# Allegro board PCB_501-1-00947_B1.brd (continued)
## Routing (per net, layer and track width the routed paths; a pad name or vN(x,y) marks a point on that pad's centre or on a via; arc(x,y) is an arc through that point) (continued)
GND_USB_A: length 27.7
  BOTTOM w0.508: J26.S4 45.09,24.7 C301.1 R250.1
  BOTTOM w1.524: J26.S1 J26.S3 41.44,21.14 43.31,21.14 J26.S4 J26.S2
GND_USB_CONN: length 14.5
  TOP w0.381: J11.S1 126.18,104.97 J11.S4 J11.S5 J11.S6 128.53,111.47 ; C242.1 R163.1 125.73,111.81 J11.S2 128.53,111.47 ; 128.53,111.47 J11.S3
PVCC_ENET_CAP: length 1.5
  TOP w0.254: U7.H14 57.46,84.18 v2(57.28,84.36)
  BOTTOM w0.254: C115.1 57.73,83.91 v2(57.28,84.36)
PVCC_EPDC_LCD_CAP: length 1.4
  TOP w0.254: v2(59.36,88.42) U7.N17
  BOTTOM w0.305: v2(59.36,88.42) 59.36,87.77 C116.1
PVCC_GPIO_CAP: length 1.6
  TOP w0.305: U7.V10 64.84,87.36 v2(64.71,87.48)
  BOTTOM w0.305: v2(64.71,87.48) 63.99,88.2 C100.1
PVCC_I2C_SPI_UART_CAP: length 2.1
  TOP w0.102: 63.68,85.24 U7.R9
  TOP w0.254: v2(63.68,85.24) 63.68,85.24 U7.R9
  BOTTOM w0.254: v2(63.68,85.24) 63.26,85.66 C128.1
PVCC_SAI_SD_CAP: length 1.4
  TOP w0.254: U7.J9 61.16,81.89 61.16,81.58 v2(61.13,81.56)
  BOTTOM w0.254: v2(61.13,81.56) 61.47,81.9 61.84,81.9
VCCI_EMMC: length 1.2
  TOP w0.081: U10.C2 70.9,63.44 70.37,63.97 70.37,64.02 v1(70.32,64.06)
VDD_1P2_CAP: length 2.3
  TOP w0.254: U7.H12 58.87,83.62 v2(58.86,83.63) ; v2(64.76,86.3) U7.U9
  BOTTOM w0.254: v2(58.86,83.63) 58.88,83.65 58.98,83.65 C88.1 ; C89.1 64.76,86.54 v2(64.76,86.3)
VDD_1V8: length 212.5
  TOP w0.152: U5.39 15.08,82.42 v1(14.93,82.27)
  TOP w0.254: U50.1 10.8,67.52 8.72,69.61 8.72,75.1 8.94,75.32 9.58,75.32 10.18,74.72 ; R682.2 v1(102.84,12.32)
  TOP w0.305: v2(61.54,82.92) 61.74,83.11 U7.L9 v2(62.54,83.11) ; U45.3 26.44,56.58 26.33,56.7 C461.1 25.68,56.51 v1(25.27,56.1) 24.71,55.54 R639.1 ; v1(75.66,92.15) 75.66,92.15 75.66,92.08 75.61,92.02 74.53,92.02 R607.1 ; v1(72.84,94.76) 72.81,94.74 72.49,94.74 R605.1 ; 81.46,99.15 U42.3 ; v1(77.38,99.36) 76.87,99.86 C407.1 76.49,99.84 76.49,99.41 77.58,98.31 ; 78.55,100.17 79,99.73 ; 80.74,95.12 80.27,95.59 U42.20 ; R638.1 R640.2
  TOP w0.381: R638.1 33.77,55.01 v1(33.88,55.12)
  TOP w0.457: M1.38 121.07,15.17 121.07,15.16
  TOP w0.508: 78.55,100.17 77.91,100.82 C509.1 77.97,101.13 C406.1 78.97,102.11 v1(79.6,102.74) ; v1(122.27,9.02) 122.14,9.02 121.75,8.63 121.75,8.5 121.74,8.49 FB39.2 ; 121.07,15.16 C216.1 v1(123.23,15.16) ; v1(82.01,93.55) C409.1 80.74,94.82 80.74,95.12 ; FB36.2 v1(5.83,38.33) ; 81.46,99.15 81.46,99.48 C410.1 81.72,99.78 v1(82.2,100.27) ; v3(77.83,73.28) 77.8,73.28 R45.1 78.66,72.42 79.46,73.22 R325.1 78.86,73.85 v3(78.37,73.85) ; C574.1 v1(89.45,51.82)
  L3_INT_1 w0.254: v1(20.99,75.89) 19.87,75.89 15.63,80.13 15.63,81.58 v1(14.93,82.27)
  L4_PWR_1 w0.254: v1(20.99,75.89) 20.99,75.87 19.59,74.46 19.59,70.58 20.51,69.66 25.4,69.66 35.02,79.28 35.02,85.41 38.58,88.97 52.8,88.97 53.81,89.98 54.23,89.98 54.69,90.44 56.09,90.44 56.98,89.55 59.57,89.55 59.71,89.42 61.37,89.42 61.66,89.71 62.97,89.71 63.3,90.04 64.29,90.04 66.79,87.53 66.79,86.62 65.27,85.09 65.27,83.45 64.49,82.67
  BOTTOM w0.178: 102.55,63.5 U55.A2
  BOTTOM w0.254: v3(80.54,81.18) 79.75,80.39 77.44,80.39 76.28,81.55 R32.1 ; 126.08,30.35 99.41,30.35 96.89,27.84 96.89,12.81 97.65,12.05 102.57,12.05 v1(102.84,12.32) 102.84,12.45 102.81,12.47 R710.2 R709.2 R708.2 R707.2 R711.2
  BOTTOM w0.305: v2(62.54,83.11) 63.08,83.65 63.08,83.83
  BOTTOM w0.381: Q39.1 12.72,50.37 R636.2 v1(12.67,49.66)
  BOTTOM w0.406: FB35.1 5.66,51.65 6.53,50.77 7.93,50.77 9.52,52.36 12.13,52.36 12.72,51.78 Q39.1
  BOTTOM w0.508: C575.1 88.9,48.39 v1(89.45,48.93)
  BOTTOM w0.635: v1(101.39,62.68) C561.1 102.55,63.5
  vias: v1(25.28,53.51) v1(25.3,52.13) v1(29.28,56.33) v1(114.65,48.77) v1(114.65,47.12) v1(114.65,45.47) v1(115.41,49.28) v1(115.41,47.62) v1(115.41,45.97) v3(11.41,73.8) v3(11.44,71.16) v3(11.49,69.75) v3(11.46,68.46) v3(12.54,72.52) v3(12.59,69.77) v3(12.54,68.45) v3(14.83,72.52) v3(14.83,71.12) v3(14.84,69.86) v3(16.22,72.52) v3(16.22,71.12) v3(16.22,69.85) v3(16.24,68.47) v3(81.4,81.18) v3(81.65,82.3) v3(82.19,81.53)
VDD_1V8_SNS: length 21
  TOP w0.203: U5.5 19.91,86.27 19.97,86.2 21.08,86.2 v1(21.3,85.99)
  TOP w0.254: 9.82,76.13 9.41,75.73 8.65,75.73 8.31,75.39 8.31,69.44 8.32,69.43 8.32,69.32 10.69,66.96 16.19,66.96 16.28,66.87 16.99,66.87 U50.2
  BOTTOM w0.508: v1(21.3,85.99) 21.3,85.76 21.56,85.5 C546.1
  vias: v1(11.6,79.3)
VDD_1V35: length 139.6
  TOP w0.152: U5.41 15.88,83 v1(15.78,82.91)
  TOP w0.254: v2(60.46,94.77) 60.46,94.77 U7.Y21 ; v2(73.76,104.37) 73.31,104.82 U8.C1 ; v2(66.34,106.43) 66.35,106.42 U8.E9 ; U7.U21 58.87,93.18 v2(58.87,93.18) ; U7.AA19 62.06,94.24 v2(62.05,94.24) ; v2(54.97,105.24) 55.35,105.62 U9.D2 ; v2(59.4,93.71) 59.4,93.71 U7.V21 ; U7.W21 59.93,94.24 v2(59.93,94.24) ; U7.AA18 62.59,93.7 v2(62.58,93.71) ; U9.B2 v2(54.96,104.41) ; 19.52,74.17 19.22,73.86 U50.14 ; v2(49.17,112.82) 49.17,112.82 U9.N9 ; v2(65.72,113.12) 66.02,112.82 U8.N9 ; U8.A8 v2(67.26,102.76) ; U9.C9 49.7,104.86 v2(49.21,104.86) ; v2(85.56,116.08) 87.11,116.08 R716.2 ; U7.AA21 60.99,95.3 v2(60.99,95.3) ; U9.F1 56.64,107.22 v2(56.75,107.11) ; U8.F1 73.31,107.22 v2(73.79,106.74) ; v2(68.95,107.57) 68.51,108.02 U8.G7 ; U8.B2 72.51,104.02 v2(72.91,103.61) ; v2(67.32,110.02) 67.71,110.41 U8.K8 ; v2(54.1,97.1) 53.78,97.42 53.78,98.33 53.05,99.06 TP20.1 ; v2(49.16,114.42) U9.R9 ; U7.AA20 61.53,94.77 v2(61.52,94.77) ; U8.H9 v2(67.32,109.22) ; U8.R1 v2(72.91,114.82) ; v2(63.11,93.18) 63.12,93.18 U7.AA17 ; v2(49.14,106.44) 49.17,106.42 U9.E9 ; U7.T21 58.34,92.65 v2(58.34,92.65) ; v2(66.38,104.81) 66.38,104.82 U8.C9 ; v2(72.9,105.21) 72.51,105.6 U8.D2 ; v2(50.94,110.03) 50.56,110.42 U9.K8 ; v2(56.71,103.21) 56.7,103.22 U9.A1 ; U7.AA16 63.65,92.65 v2(63.64,92.65) ; U9.R1 v2(57.04,114.42) ; v2(66.15,115.21) 66.91,114.45 U8.R9 ; U8.H2 v2(72.9,108.43) ; U8.N1 v2(72.91,113.22) ; U9.H9 v2(49.21,108.82) ; U8.A1 v2(73.72,102.8) ; U8.D9 v2(66.37,105.62) ; U9.C1 56.75,104.82 v2(56.76,104.83) ; U8.K2 v2(72.94,109.98) ; U9.D9 v2(50.14,106.01) ; U9.G7 v2(51.78,108.45)
  TOP w0.279: U51.2 82.4,114.02 82.4,114.82 82.64,115.06
  TOP w0.305: U9.A8 50.55,103.13 v2(50.55,102.65) ; U9.N1 v2(57.04,112.82) ; U9.K2 v2(54.95,110.82) ; U9.H2 v2(54.95,108.41)
  TOP w0.508: 82.64,115.06 82.64,115.49 C533.1
  L6_INT_2 w0.254: v1(15.78,82.91) 12.66,82.91 12.1,83.46 9.67,83.46 9.2,83.93 9.2,86.68 9.47,86.94 9.78,86.94 10.08,87.24 10.08,87.66 8.79,88.95 8.79,90.07 9.61,90.88 10.9,90.88 11.35,91.33 16.04,91.33 18.02,93.31 18.02,99.22 21.47,102.68 35.95,102.68 38.95,105.68 48.4,105.68 v2(49.21,104.86)
  BOTTOM w0.254: v2(73.76,104.37) 74.31,104.37 C159.1 ; v2(54.95,110.82) 55.61,110.82 C150.1 ; v2(49.17,112.82) 48.99,112.64 C157.1 ; C164.1 73.04,114.68 v2(72.91,114.82) ; C153.1 66.81,104.38 v2(66.38,104.81) ; C143.1 50.88,106.01 v2(50.14,106.01) ; v2(56.71,103.21) 56.8,103.11 C144.1 ; v2(65.72,113.12) 65.98,113.38 C174.1 ; v2(57.04,112.82) 56.31,112.82 C149.1 ; C168.1 69.63,107.57 v2(68.95,107.57) ; v2(72.91,113.22) 73.52,113.22 C161.1 ; v2(72.9,108.43) 73.08,108.43 73.5,108.84 C166.1 ; C142.1 50.94,110.77 v2(50.94,110.03) ; C163.1 72.73,105.04 v2(72.9,105.21) ; C151.1 56.03,104.83 v2(56.76,104.83) ; C165.1 72.94,109.63 v2(72.94,109.98) ; v2(57.04,114.42) 57.03,114.42 C147.1 ; C155.1 54.17,104.41 v2(54.96,104.41) ; C175.1 48.94,109.09 v2(49.21,108.82) ; C176.1 57.16,107.11 v2(56.75,107.11) ; C167.1 67.19,110.15 v2(67.32,110.02) ; v2(73.79,106.74) 74.16,107.11 C162.1 ; C158.1 66.56,106.21 v2(66.34,106.43) ; C160.1 54.91,108.41 v2(54.95,108.41) ; v2(66.15,115.21) 65.66,115.7 65.66,115.77 C145.1 ; R85.2 54.1,96.57 v2(54.1,97.1)
  BOTTOM w0.305: v2(49.21,104.86) 48.51,104.86 C172.1 ; v2(73.72,102.8) 74.13,102.39 C178.1 ; C177.1 50.23,102.33 v2(50.55,102.65) ; C146.1 53.06,111.51 v2(53,111.51) ; v2(67.32,109.22) 67.33,109.21 C170.1 ; v2(49.14,106.44) 48.7,106 C152.1 ; v2(72.91,103.61) 72.91,102.88 C180.1 ; v2(49.16,114.42) 49.2,114.38 C169.1 ; TP19.1 67.82,101.83 C156.1 67.81,102.21 v2(67.26,102.76)
  vias: v2(85.56,115.32) v3(20.41,73.41) v3(20.41,70.87) v3(21.68,74.68) v3(21.68,72.14) v3(22.95,73.41) v3(22.95,70.87) v3(23.23,75.86) v3(24.22,72.01) v3(24.48,74.68) v3(25.62,73.28) v3(25.75,75.56)
VDD_1V35_SNS: length 5.9
  TOP w0.254: U50.15 18.56,74.11 18.38,74.3
VDD_3V3: length 232.8
  TOP w0.127: U50.16 v1(17.91,69.43)
  TOP w0.254: U10.E6 71.96,61.18 v1(71.64,60.86) 71.26,61.25 U10.F5 71.25,61.31 ; v2(63.65,84.18) 63.64,84.18 U7.N9 ; v2(63.59,82.89) 63.56,82.86 63.37,82.86 U7.M8 ; U7.F10 58.87,80.47 58.87,80.47 v2(58.87,80.44) ; v2(57.37,84.9) 57.09,84.9 U7.H16 ; U10.J10 72.11,58.33 v1(72.11,57.92) ; R692.1 v1(117.56,65.91) ; U7.F12 v2(57.81,82.58) ; U24.10 93.19,40.29 ; 71.25,58.49 71.06,58.29 v1(71.06,57.97) ; v1(33.7,91.01) 37.69,95 43.78,95 R740.2 44.08,94.83 R739.2 ; 94.79,42.26 U24.8 ; R750.2 24.58,94.34 v3(24.35,94.11) ; R749.2 v1(11.52,90.68) ; U7.F9 v2(59.4,79.93)
  TOP w0.305: U7.K18 57.03,87.08 v2(57.24,87.08) 57.53,87.08 57.81,87.36 ; 57.81,87.36 U7.L17 ; 57.81,87.36 U7.L17 ; U7.L17 57.81,87.59 v2(58.23,88.01) 58.22,88.01 U7.M18 ; U7.L17 57.81,87.34 v2(58.13,87.03) ; U7.P8 64.17,84.18 v2(64.17,84.71) 64.18,84.7 64.71,84.7 U7.T8 65.24,85.37 64.89,85.71 v2(64.89,85.72) ; C460.1 31.94,57.08 U45.7 ; 73.19,77.91 R387.2 73.54,77.91 v1(73.95,77.5)
  TOP w0.381: v1(14.83,65.02) 15.05,65.25 C566.1 16.32,65.25 16.64,65.57 U50.4 ; v1(31.62,57.78) 31.69,57.78 C460.1 ; v1(73.68,71.99) 73.64,72.03 73.6,72.03 72.9,72.73 R235.2 ; v1(3.17,32.41) R296.2 R295.2 ; v1(70.83,69.34) 70.45,68.96 69.64,68.96 R231.2 ; v3(24.35,94.11) 24.1,94.36 R686.1 ; R658.1 v1(117.31,47.24) ; FB21.2 v1(47.59,35.31) ; R674.1 v1(124.3,48.89)
  TOP w0.406: 94.79,42.26 94.79,42.8 94.69,42.9 C268.1 94.69,43.32 v1(95.3,43.32) ; 93.19,40.29 92.43,40.29 C267.1 v1(92.42,40.94)
  TOP w0.508: SW2.12 15.32,18.28 ; SW2.12 13.92,17.53 ; SW2.12 16.71,17.53 ; SW2.12 15.32,16.78 ; 13.92,9.91 SW2.9 ; SW2.9 15.32,9.16 ; SW2.9 15.32,10.66 ; SW2.9 16.71,9.91 ; C574.2 v1(87.27,51.82) ; SW2.14 15.32,23.36 ; SW2.14 16.71,22.61 ; SW2.14 13.92,22.61 ; SW2.14 15.32,21.86 ; U25.5 73.67,21.94 73.59,21.87 C505.1 v1(72.1,21.21) ; 15.32,14.24 SW2.11 ; SW2.11 13.92,14.99 ; SW2.11 16.71,14.99 ; SW2.11 15.32,15.74 ; U31.1 121.95,45.3 C391.1 v1(121.86,44.2) ; SW2.15 15.32,25.9 ; SW2.15 16.71,25.15 ; SW2.15 15.32,24.4 ; SW2.15 13.92,25.15 ; 15.32,11.7 SW2.10 ; SW2.10 16.71,12.45 ; SW2.10 15.32,13.2 ; SW2.10 13.92,12.45 ; R727.2 v1(24.86,66.17) ; H5.1 54.83,125.5 C577.1 ; 15.32,19.32 SW2.13 ; SW2.13 16.71,20.07 ; SW2.13 13.92,20.07 ; SW2.13 15.32,20.82 ; U41.8 86.73,59.05 C408.1 85.73,59.21 v1(85.72,59.22) ; 13.92,27.69 SW2.16 ; SW2.16 15.32,26.94 ; SW2.16 16.71,27.69 ; R224.2 v1(77.97,22.83) ; v3(100.04,45.14) 100.04,44.24 FB41.1 ; R46.1 77.45,72.14 v3(76.96,72.14)
  L3_INT_1 w0.508: 53.7,126.38 H5.1 55.96,126.38
  L6_INT_2 w0.127: v1(17.91,69.43) v1(19.87,69.43)
  L6_INT_2 w0.254: v3(9.49,95.5) 9.49,95.5 5.38,91.39 5.38,82.18 5.37,82.17 5.37,79.46 9.57,75.26 25.23,75.26 25.51,74.98 26.72,74.98 v1(27.05,75.31)
  BOTTOM w0.127: 18.31,81.41 18.16,81.41 R685.1 ; U52.16 v1(19.87,69.43)
  BOTTOM w0.229: U19.8 103.72,105.93 ; U17.8 113.97,109.47
  BOTTOM w0.254: v2(63.65,84.18) 64.36,84.18 C127.1 ; v1(117.56,65.91) 117.56,55.63 v1(124.3,48.89) ; R751.1 17.06,81.05 17.8,81.05 R685.1 18.28,81.38 18.31,81.41 v1(18.79,81.41) ; v2(63.59,82.89) 63.87,83.17 C118.1 ; R732.2 21.53,63.98 v1(21.94,64.39) ; v2(57.37,84.9) 57.36,84.9 C113.1 ; R169.2 111.22,102.51 R170.2 v1(108.32,102.51) ; U52.1 21.1,67.52 22.04,68.46 22.04,70.78 25.56,74.3 26.03,74.3 v1(27.05,75.31) ; C98.1 64.57,85.1 64.18,84.71 v2(64.17,84.71) ; v1(109.95,100.63) 110.41,101.09 113.09,101.09 113.63,101.64 R168.2 ; v2(64.89,85.72) 65,85.72 65.34,86.07 C99.1
  BOTTOM w0.305: v2(57.24,87.08) 57.04,86.88 C109.1 ; v1(49.63,75.47) 49.85,75.69 R33.2 49.09,77.1 R34.2 ; C101.1 56.07,82.11 56.13,82.04 56.91,82.04 57.46,82.58 v2(57.81,82.58) ; C114.1 58.13,87.11 v2(58.13,87.03) ; v2(58.23,88.01) 58.62,88.4 C112.1 ; R64.2 63.02,72.24 v1(63.02,71.9) ; R63.2 65.49,73.87 65.49,74.66 v1(65.44,74.71) 65.66,74.71 R61.2 66.07,75.12 R62.2 ; C122.1 59.54,79.93 v2(59.4,79.93) ; v2(58.87,80.44) 58.24,81.07 C117.1
  BOTTOM w0.381: U52.4 21.01,65.57 21.28,65.3 ; R637.2 13.02,54.86 v1(13.49,54.39) ; R171.2 106.95,102.41 v1(106.42,102.41)
  BOTTOM w0.406: v1(113.63,108.32) C241.1 112.98,108.71 113.75,109.47 113.97,109.47 ; v1(105.43,104.4) 105.43,104.4 C245.1 103.72,105.41 103.72,105.93
  BOTTOM w0.508: v1(21.94,64.39) 22.19,64.64 C567.1 21.28,65.3 ; C189.1 45.48,105.51 C190.1 46.14,104.86 U11.8 ; C189.1 v1(45.48,107.49) ; C189.1 v1(44.42,106.43) ; R253.2 v1(54.7,24.13) ; v1(54.31,16.37) 54.26,16.42 Q25.1 ; v1(14.06,66.39) 14.06,66.42 14.42,66.78 R731.2 ; R257.2 v1(54.07,20.07) ; v1(87.34,48.89) 87.85,48.39 C575.2 ; R252.2 v1(59.74,24.16) ; v1(41.74,87.76) 41.78,87.76 41.86,87.68 44.53,87.68 46.19,89.34 R92.1 ; R255.2 v1(58.47,24.16)
  vias: v1(22.32,40.77) v1(23.97,41.02) v1(30.53,53.3) v1(30.51,52.48) v1(31.96,53.24) v1(31.97,52.49) v1(33.75,62.1) v1(33.75,60.71) v1(33.75,59.31) v1(41.37,65.91) v1(42.38,67.06) v1(55.47,51.82) v1(55.72,65.53) v1(60.93,53.59) v1(62.32,52.32) v1(68.8,55.5) v1(69.64,54.97) v1(69.76,55.82) v1(85.56,111.12) v1(94.78,55.91) v1(95.4,55.34) v1(98.12,126.44) v1(98.8,124.1) v1(99.79,126.44) v1(100.45,124.1) v1(101.46,126.44) v1(102.13,124.1) v1(103.14,126.44) v1(103.8,124.1) v1(104.81,126.44) v1(105.47,124.1) v1(106.48,126.44) v1(107.14,124.1) v1(108.15,126.44) v1(108.82,124.1) v1(109.83,126.44) v1(110.49,124.1) v1(111.5,126.44) v2(61.18,55.75) v2(61.43,58.17) v2(62.32,54.86) v2(62.45,57.02) v3(7.59,98.04) v3(7.57,95.5) v3(8.2,96.8) v3(9.36,98.04) v3(10.25,96.77) v3(11.14,98.04) v3(11.27,95.5) v3(12.03,96.77) v3(12.92,98.04) v3(12.92,95.5) v3(13.17,21.34) v3(13.17,18.8) v3(13.17,16.13) v3(13.17,13.59) v3(13.17,11.05) v3(13.17,8.25) v3(14.09,23.98) v3(17.75,27.81) v3(17.75,25.53) v3(17.75,21.08) v3(17.75,18.8) v3(17.75,16.64) v3(17.75,14.35) v3(17.75,12.19) v3(17.75,9.91) v3(24.22,91.06) v3(25.87,91.06) v3(26.26,94.11) v3(125.44,21.72) v3(125.44,20.95)
VDD_3V3_LCD: length 20.3
  TOP w0.254: R656.1 7.21,58.04 7.56,57.68 C392.1
  TOP w0.381: C558.1 16.03,46.32 v1(16.03,47.05)
  TOP w0.508: U33.5 8.44,57.6 C392.1 v1(8.35,56.64) ; v3(9.39,39.12) 9.59,39.12 10.19,39.72 C264.1 11.8,39.72 C263.1 11.96,39.07 12.31,38.71 14.08,38.71 v1(14.4,39.03)
  L6_INT_2 w0.508: v1(16.03,47.05) 15.7,47.38 v1(15.7,49.56)
  BOTTOM w0.305: J14.45 9.1,38.83 v3(9.39,39.12) 9.32,39.12 9.11,39.33 J14.46
  BOTTOM w0.381: v1(15.7,49.56) 15.7,50.92 16.03,51.25 U23.10 ; U23.7 v1(16.03,47.05)
  vias: v1(21.68,45.72) v1(22.7,44.96)
VDD_3V3_PERI: length 28.3
  TOP w0.254: 123.3,70.38 R694.2 C531.1
  BOTTOM w0.508: J8.24 v3(104.92,81.58) ; J8.41 v1(98.12,73.44) ; D7.2 D6.2 126.49,86.9 126.2,86.61 D5.1 125.43,82.15 124.85,81.58 v3(116.92,81.58) J8.2 ; C201.1 v1(98.72,72.26) ; J8.39 v1(98.92,73.41) ; J8.52 v3(93.72,81.58)
  vias: v1(30.66,49.41) v1(31.84,49.4) v1(31.84,48.51) v1(64.25,39.65) v1(65.98,39.64) v1(65.98,38.66) v3(92.55,82.21) v3(122.04,80.85) v3(122.08,79.09) v3(122.07,75.11) v3(122.1,77.07) v3(123.64,80.93) v3(123.62,79.02) v3(123.64,77.12) v3(123.62,75.22) v3(125.54,80.93) v3(125.54,77.12) v3(125.52,75.22) v3(125.86,78.91) v3(127.44,80.93) v3(127.44,79.03) v3(127.48,77.2) v3(127.48,75.13)
VDD_3V3_SD: length 149.1
  TOP w0.508: 12.34,87.72 10.88,89.19 10.4,89.19 C45.1 9.5,89.33 v1(9.39,89.22)
  L6_INT_2 w0.508: v1(101.94,65.53) 102.14,65.73 107.26,65.73 109.19,67.66 109.19,86.78 99.71,96.27 84.68,96.27 81.8,99.15 78.52,99.15 77.98,98.61 74.65,98.61 73.51,99.74 48.18,99.74 45.78,102.14 22.14,102.14 18.76,98.76 18.76,92.37 15.62,89.23 12.81,89.23 12.81,89.23 9.4,89.23 v1(9.39,89.22)
  BOTTOM w0.178: 102.76,64.65 103.1,64.32 U55.A1
  BOTTOM w0.635: v1(101.94,65.53) C560.1 102.76,64.65
VDD_3V3_SNS: length 69.7
  TOP w0.203: U5.31 12.7,86.67 12.35,87.02 12.34,87.02 12.34,87.02 11.31,87.02 v1(11.09,87.24)
  L6_INT_2 w0.254: v1(17.05,94.82) 16.81,94.82 15.98,93.98 10.01,93.98 6.44,90.41 6.44,81.44 11.35,76.53 23.47,76.53 23.63,76.37 26.77,76.37 27.61,75.53 27.61,74.93 v1(27.27,74.58)
  BOTTOM w0.254: v1(27.27,74.58) 26.64,73.95 26.64,73.15 22.57,69.09 22.57,68.19 21.26,66.87 20.79,66.87 U52.2
  BOTTOM w0.381: v1(11.09,87.24) 11.4,87.55 11.4,88.57 14.38,91.55 14.38,92.59 16.61,94.82 v1(17.05,94.82)
VDD_5V: length 28.5
  TOP w0.508: v1(71.7,26.94) FB37.2 v1(70.96,27.69) ; v3(9.38,40.13) 10.03,40.79 C262.1 10.75,40.79 10.96,40.99 v3(11.09,40.99) 11.24,40.99 11.62,41.38 C261.1 11.9,42.14 v3(11.51,42.54) ; v3(103.07,35.31) FB40.1
  BOTTOM w0.254: U52.11 16.99,66.87 15.91,66.87 15.48,67.31 15.46,67.31 13.43,69.34 13.43,70.23 5.95,77.71 v3(5.95,80.85)
  BOTTOM w0.305: 8.3,40.34 9.16,40.34 9.36,40.13 v3(9.38,40.13) 9.07,39.83 J14.47
  BOTTOM w0.635: 57.12,12.37 C525.1
  vias: v1(55.9,12.37) v1(57.17,11.1) v3(1.43,85.22) v3(1.43,83.82) v3(1.43,82.42) v3(2.25,80.85) v3(3.19,82.42) v3(3.65,86.49) v3(4.03,80.85) v3(4.79,82.42) v3(7.02,81.68)
VDD_5V_SNS: length 24.5
  BOTTOM w0.254: U52.12 16.17,67.52 14.08,69.61 14.08,72.06 9.71,76.43 8.54,76.43 7.89,77.09 7.87,77.09 7.57,77.39 7.57,77.41 6.67,78.31 6.67,81.13 5.9,81.89 v1(5.9,86.21)
  vias: v1(10.35,85.48) v1(10.42,84.14) v1(10.99,84.9) v1(11.25,84.12) v1(11.45,85.61) v1(11.87,84.86) v1(21.01,87.72) v1(21.98,86.64) v1(22.51,88.57) v1(22.72,86.8)
VDD_CAN: length 2.7
  TOP w0.508: U25.3 74.32,25.6 74.16,25.76 C279.1 74.16,27.58 C570.1
VDD_CLKGEN_1V8: length 6
  TOP w0.127: R705.2 123.89,9.52 C527.1
  TOP w0.508: Y5.4 123.77,10.93 C527.1 123.77,8.31 C528.1 123.66,8.2 122.59,8.2 FB39.1
VDD_CSI_2V8_1: length 6.1
  TOP w0.254: 6.89,43.95 J20.3
  TOP w0.406: C445.1 10.93,43.43 9.2,43.43 C444.1 9.18,43.43 8.07,43.43 FB31.2 7.82,43.33 7.2,43.95 6.89,43.95
VDD_CSI_2V8_2: length 4.3
  TOP w0.254: J20.5 7.03,44.75
  TOP w0.406: C354.1 9,45 C501.1 8.96,45 7.9,45 FB32.2 7.52,44.75 7.03,44.75
VDD_CSI_XCLK: length 4.2
  BOTTOM w0.406: FB35.2 4.42,50.43 R623.1 C448.1 3.37,48.69 Y4.4
VDD_DCJACK_5VIN: length 17.3
  TOP w1.27: J1.1 26.05,119.07 ; J1.1 26.05,116.45 ; J1.1 29.06,117.76 ; J1.1 23.04,117.76
  BOTTOM w1.27: J1.1 26.05,119.07 ; J1.1 26.05,116.45 ; J1.1 23.04,117.76 ; J1.1 29.06,117.76
  vias: v3(21.56,120.65) v3(21.56,117.09) v3(21.56,113.41) v3(22.45,119.38) v3(22.45,115.19) v3(23.33,120.65) v3(23.33,113.41) v3(24.22,119.38) v3(24.22,115.19) v3(25.11,120.65) v3(25.11,113.41) v3(26,115.19) v3(26.89,120.65) v3(26.89,113.41) v3(27.78,119.38) v3(27.78,115.19) v3(28.67,120.65) v3(28.67,113.41) v3(29.56,119.38) v3(29.56,115.19) v3(30.32,120.65) v3(30.45,117.09) v3(30.45,113.41) v3(31.34,119.38) v3(31.34,115.19) v3(31.94,113.42) v3(32.1,120.65) v3(33.29,115.19)
VDD_DDR_VTT: length 6.3
  TOP w0.254: U51.5 80.88,114.41 v1(80.61,114.68)
  TOP w0.279: 81.71,114.98 81.71,114.9 81.88,114.73 U51.3
  TOP w0.508: C539.1 81.66,115.09 81.66,115.03 81.71,114.98
  L6_INT_2 w0.381: v1(80.61,114.68) 81.88,115.95 v1(81.88,117.86)
VDD_HOST_VBUS: length 4.3
  TOP w0.305: U7.C10 v2(57.28,78.87)
  BOTTOM w0.305: v2(57.28,78.87) 56.94,78.53 56.79,78.53 C123.1 56.06,77.8 55.64,77.8 R71.2 54.73,76.89 R69.1
VDD_LDO_1V5: length 31.5
  BOTTOM w0.254: U52.14 18.56,72.38 24.22,78.04 24.22,84.2 25.75,85.72 v1(27.78,85.72)
  BOTTOM w0.508: J8.28 v3(103.32,84.88) ; v3(115.44,86.37) C503.1 115.32,85.36 J8.6 ; J8.48 95.32,84.77 94.24,85.85 C504.1 94.09,85.91 94.09,86.63 v3(94.2,86.74)
  vias: v1(28.81,84.58) v1(28.92,86.74) v1(29.56,85.22) v3(109.66,89.27) v3(110.97,89.32) v3(112.64,89.32) v3(114.31,89.32) v3(115.95,89.28)
VDD_LDO_1V5_SNS: length 18
  BOTTOM w0.254: v1(24.88,84.05) 24.88,77.38 24.86,77.36 24.86,76.94 24.88,76.91 24.88,76.22 19.22,70.56 U52.15
VDD_LDO_2V5:
  vias: v3(28.8,27.3) v3(29.68,26.42) v3(58.51,39.12) v3(58.51,38.1) v3(59.66,38.61)
VDD_LDO_2V8: length 1.4
  TOP w0.508: v1(8.35,46.48) 7.84,45.97 FB32.1 ; FB31.1 v1(7.35,42.53)
  vias: v1(22.99,48.39) v1(23.93,48.71) v1(24.86,48.39)
VDD_LPSR_1P0_CAP: length 1.4
  TOP w0.305: v2(71.07,87.36) 71.07,87.36 U7.AC5
  BOTTOM w0.305: 71.8,87.63 71.35,87.63 v2(71.07,87.36)
VDD_LPSR_IN: length 3.2
  TOP w0.254: U7.W6 68.42,85.77 v2(68.42,85.76)
  BOTTOM w0.406: R32.2 76.44,83.13 C96.1 76.44,83.7 75.89,84.25 v1(75.89,84.28)
VDD_OTG1_1P0_CAP: length 2.2
  TOP w0.254: U7.H10 v2(59.54,82.45)
  BOTTOM w0.305: v2(59.54,82.45) 59.54,81.83 C119.1 60.28,81.09 C120.1
VDD_OTG2_1P0_CAP: length 2.1
  TOP w0.254: U7.J11 v2(60.44,83.11)
  BOTTOM w0.305: C125.1 61.09,83.31 C125.1 ; C125.1 60.94,83.16 60.49,83.16 v2(60.44,83.11) ; C125.1 61.09,83.32 C126.1
VDD_OTG_VBUS: length 4.4
  TOP w0.305: v2(57.81,78.34) 57.85,78.34 57.86,78.34 U7.C8
  BOTTOM w0.305: R65.1 55.78,75.27 56.5,75.99 57.48,76.98 C121.1 57.48,77.46 57.81,77.79 v2(57.81,78.34)
VDD_PHY_1V0: length 9
  TOP w0.254: U13.31 35.28,38.6 v1(35.15,38.73) ; U13.42 32.08,34.77 30.99,34.77 ; U13.6 v1(35.28,30.23)
  TOP w0.508: v1(30.88,36.07) C310.1 30.29,35.92 C307.1 30.32,34.77 30.99,34.77
  BOTTOM w0.483: v1(35.15,38.73) 35.15,39.47
  BOTTOM w0.508: C311.1 37.03,29.31 C302.1 35.28,29.69 v1(35.28,30.23) ; 35.15,39.47 C303.1
  vias: v1(39.28,37.93) v1(40.28,41.11) v1(40.31,41.96)
VDD_SD: length 8.9
  TOP w0.254: v2(59.94,79.38) 59.94,79.2 59.93,79.2 U7.E7
  BOTTOM w0.178: U55.B1 103.68,64.08 104.34,64.08
  BOTTOM w0.254: R100.1 R101.1 107.63,64.36 v1(107.11,64.88) ; v1(107.84,50.48) 108.39,49.93 R491.2 R99.1
  BOTTOM w0.305: v2(59.94,79.38) 60.46,78.85 C104.1
  BOTTOM w0.635: v1(105.38,64.82) C559.1 104.34,64.08
VDD_SD2: length 6.1
  TOP w0.254: v2(61.51,80.87) 61.39,80.99 U7.H8
  TOP w0.508: v3(79.89,76.5) 79.89,76.47 79.52,76.09 79.52,74.53 80.38,73.67 80.38,72.76 80.17,72.54 80.17,72.54
  BOTTOM w0.254: C108.1 61.61,80.12 61.61,80.77 v2(61.51,80.87)
VDD_SD3: length 43.9
  TOP w0.076: 67.34,62.73 68.12,61.95 v1(68.16,61.95)
  TOP w0.127: R93.1 67.52,67.71 R94.1 67.14,67.32 66.77,66.96 66.77,63.29 67.34,62.73
  TOP w0.254: v1(72.36,61.62) 72.36,61.72 72.49,61.84 U10.C6 72.67,62.02 ; 68.61,59.38 68.61,59.37 U10.N4 ; 68.61,59.38 68.95,59.71 69.03,59.71 v1(69.05,59.74) ; 68.61,59.38 U10.M4 ; U10.P5 68,58.06 68,57.88 v1(68.05,57.83) ; v1(66.89,59.1) 67.63,59.1 U10.P3 ; v2(62.29,82.64) 62.06,82.41 U7.K8
  TOP w0.508: R46.2 v1(78.59,69.98) ; v3(80.93,70.15) R45.2
  L6_INT_2 w0.508: v3(81.07,79.2) 81.04,79.2 80.17,80.07 76.74,80.07 75.8,81.01 70.31,81.01 70.13,81.19 68.49,81.19
  BOTTOM w0.254: C110.1 62.63,82.64 v2(62.29,82.64)
  BOTTOM w0.406: v1(72.36,61.62) 72.45,61.7 72.79,61.7 C187.1
  BOTTOM w0.508: C185.1 67.98,57.39 67.98,57.76 v1(68.05,57.83) ; C188.1 65.12,57.33 C184.1 v1(66.89,59.1) ; v3(80.93,70.15) 81.28,70.49 81.28,79 v3(81.07,79.2) ; v1(69.05,59.74) 68.8,59.49 C186.1
VDD_SD_CON: length 17.3
  TOP w0.381: v1(102.38,54.18) 102.38,51.62 TP83.1
  BOTTOM w0.254: R103.1 100.42,58.42 v1(101.17,57.68)
  BOTTOM w0.508: v1(107.25,54.99) 107.25,54.3 107.27,54.29 FB42.2 108.58,54.07 C195.1 108.73,53.92 C196.1 112.01,53.92 J28.4
VDD_SNVS_1P8_CAP: length 1.4
  TOP w0.305: U7.AE8 70.02,90.02 v2(70.02,90.58)
  BOTTOM w0.305: C95.1 69.92,90.58 v2(70.02,90.58)
VDD_SOC_ARM: length 106.9
  TOP w0.152: U5.47 18.28,83.42 18.7,83 18.7,82.81 v1(19.51,82.01)
  TOP w0.254: U7.F22 51.98,87.36 v2(51.98,87.36) 51.98,87.36 U7.F23 v2(51.45,87.89) ; U7.D17 54.1,83.64 53.57,83.64 v2(53.57,83.64) 53.57,83.12 U7.C17 v2(53.04,83.11) ; U50.11 20.79,66.87 21.87,66.87 23,68 27.45,68 28.54,69.09 28.54,76.83 27.79,77.58 27.79,78.17 27.94,78.31 ; U7.J23 53.57,88.95 v2(53.57,88.95) U7.J22 54.1,88.42 v2(54.1,88.42) ; U7.D20 v2(51.98,85.24) 51.98,84.71 U7.C20 51.46,84.71 v2(51.45,84.71)
  TOP w0.305: U7.T18 59.62,90.85 59.62,90.93 v2(59.63,90.93) ; U7.T18 U7.R17 59.6,89.15 59.6,89.14 v2(59.49,89.03) 59.32,89.03 U7.P18 58.38,89.97 58.38,89.98 v2(58.35,90.01) ; U7.T18 59.94,90.54 v2(60.46,90.54) 60.99,90.54 60.99,90.54 U7.U17 ; v2(61.66,90.14) 61.66,90.15 62.05,90.54 U7.V16 ; v2(61.66,90.14) 61.39,90.14 U7.U17 ; v2(61.66,90.14) 62.06,89.74 U7.U15 ; U7.F3 62.59,77.28 v2(62.59,76.75) ; U7.J4 63.65,78.87 v2(63.65,78.87) ; U7.U17 60.99,90.88 v2(60.75,91.13) 60.99,91.37 U7.V18 ; v2(62.72,89.08) 62.88,88.92 v2(63.31,88.92) ; v2(62.72,89.08) 63.11,89.48 U7.V14 ; v2(62.72,89.08) 62.32,89.48 U7.U15 ; U7.M4 v2(65.24,80.46) ; U7.R4 67.36,82.58 v2(67.36,82.58) ; v2(63.31,88.92) 63.68,88.92 U7.V12 ; v2(63.31,88.92) 63.31,88.62 U7.U13 63.11,88.42 62.81,88.11 v2(62.7,88.11) ; v2(62.06,77.28) 62.06,77.28 U7.F4 ; U7.U15 62.04,89.48 v2(61.67,89.1) ; 67.36,82.05 67.89,82.05 v2(67.89,82.05) ; U7.D14 v2(55.16,82.05) ; U7.M3 v2(65.77,79.93) ; U7.F18 v2(54.1,85.24) 54.1,85.24 U7.F19 ; 55.16,81.52 v2(54.63,81.52) ; U7.J3 64.18,78.34 v2(64.18,78.34)
  TOP w0.508: 30.65,80.52 TP79.1 ; TP79.1 32.02,80.52 ; TP79.1 31.34,79.83 ; TP79.1 31.34,81.2
  L5_PWR_2 w0.127: v2(62.06,77.28) 62.02,77.24
  L6_INT_2 w0.254: v2(51.45,87.89) 50.17,89.17 41.1,89.17 40.33,88.4 40.33,83.21 39.13,82.01 v1(19.51,82.01)
  BOTTOM w0.305: C82.1 66.17,79.53 v2(65.77,79.93) v2(65.24,80.46) ; v2(63.65,78.87) v2(64.18,78.34) 64.51,78.34 C69.1 ; v2(62.06,77.28) v2(62.59,76.75) 63.27,76.06 C68.1 ; v2(55.16,82.05) 55.39,81.83 C70.1 55.27,81.52 v2(54.63,81.52) ; v2(51.98,85.24) 51.46,84.71 v2(51.45,84.71) ; C84.1 54.59,85.72 v2(54.1,85.24) ; v2(67.36,82.58) v2(67.89,82.05) 68.54,82.05 68.64,81.95 ; v2(53.57,83.64) v2(53.04,83.11)
  BOTTOM w0.356: 52.3,82.69 C71.1 52.62,82.69 v2(53.04,83.11)
  BOTTOM w0.406: C65.1 50.93,84.1 C72.1 51.45,84.4 v2(51.45,84.71) ; v2(53.57,88.95) 53.04,89.48 53.04,89.49 C63.1 52.55,89.96 C64.1 51.06,88.47 50.87,88.47 ; 50.87,88.47 C73.1 ; 50.87,88.47 v2(51.45,87.89) v2(51.98,87.36)
  vias: v3(38.83,71.5) v3(38.83,69.09) v3(38.83,67.56) v3(39.46,68.2) v3(39.72,69.98) v3(40.6,69.22)
VDD_SOC_ARM_SNS: length 17.8
  TOP w0.254: U50.12 21.77,67.52 22.72,68.48 27.18,68.48 28.03,69.33 28.03,76.66 27.65,77.04 27.65,77.05 27.13,77.57 27.13,78.73
VDD_SPK: length 8.5
  TOP w0.254: v1(96.8,35.8) 96.79,35.81 U24.21 ; 99.84,37.44 99.49,37.79 U24.26
  TOP w0.406: v3(100.07,36.96) 100.02,37.01 100.02,37.26 99.84,37.44
  TOP w0.508: FB40.2 100.94,35.63 100.94,36.66 C270.1 100.37,36.66 v3(100.07,36.96)
  BOTTOM w0.508: v1(96.8,35.8) 97.66,36.66 C269.1 99.87,36.76 v3(100.07,36.96)
VDDA_1P0_CAP: length 2.3
  TOP w0.305: v2(69.48,83.64) 69.48,83.64 68.95,83.64 U7.V3
  BOTTOM w0.305: C86.1 69.55,83.71 v2(69.48,83.64) 69.48,83.34 C87.1
VDDA_1P8: length 6.3
  TOP w0.254: U7.W5 v2(67.89,85.24) ; v2(68.42,84.7) 68.42,84.71 U7.V5 ; U7.V6 66.83,85.24 v2(66.83,85.24)
  BOTTOM w0.254: v2(67.89,85.24) 67.49,85.64 C91.1 67.23,85.64 v2(66.83,85.24)
  BOTTOM w0.305: v2(68.42,84.7) 68.93,85.21 C107.1 68.83,85.24 v2(67.89,85.24)
  BOTTOM w0.508: D34.2 71.99,91.05 v1(70.93,91.05)
  vias: v3(76.65,84.89) v3(77.18,84.38)
VDDA_ADC_1P8: length 9.1
  TOP w0.305: v2(71.6,85.76) 71.6,85.77 U7.AB3 ; v2(72.13,86.29) 72.13,86.3 U7.AC3 ; U7.AC4 71.6,86.83 v2(71.6,86.82)
  BOTTOM w0.305: v2(71.6,86.82) 72.33,86.82 C130.1 ; C131.1 72.69,85.74 v2(72.13,86.29) ; C362.1 71.6,85.19 v2(71.6,85.76)
  BOTTOM w0.483: FB3.2 82.26,84.96
  BOTTOM w0.635: v3(78.1,85.62) 78.11,85.61 81.62,85.61 82.26,84.96
VDDA_CLKGEN_1V8: length 0.8
  TOP w0.279: v1(77.7,95.48) 77.9,95.69 78,95.69 U42.16
VDDA_PHY_1P8: length 5.1
  TOP w0.305: v2(59.39,84.16) 59.38,84.18 U7.J13 ; U7.Y12 65.77,89.48 v2(65.77,89.48) 65.77,89.47 U7.Y11 66.3,88.95 v2(66.3,88.95) 66.3,88.94 U7.Y10 66.83,88.42 v2(66.83,88.42) 66.83,88.41 U7.Y9 67.36,87.89 v2(67.36,87.89)
  BOTTOM w0.254: 59.99,84.81 C67.1 59.99,84.76 v2(59.39,84.16)
VDDA_PHY_1V8: length 24.4
  TOP w0.254: v1(39.84,31.11) 39.76,31.11 39.08,31.79 U13.13 ; U13.48 31.57,31.79
  TOP w0.508: v1(30.55,29.36) C283.1 C507.1 30.61,31.43 31.21,31.43 31.57,31.79
  L6_INT_2 w0.508: v1(30.55,29.36) 31.03,28.88 v1(41.7,28.88)
  BOTTOM w0.508: C285.1 30.22,29.36 v1(30.55,29.36) ; v1(39.84,31.11) C508.1 40.89,29.94 40.93,29.9 40.99,29.9 C284.1 41.04,29.54 v1(41.7,28.88) C280.1 44.09,28.83 FB19.1
VDDA_PHY_2V5: length 13.6
  TOP w0.254: U13.3 v1(33.78,30.23) ; U13.9 v1(36.78,30.23)
  BOTTOM w0.508: FB20.1 31.28,28.21 C286.1 32.22,28.27 C291.1 32.1,29.92 C290.1 32.25,31.06 33.57,31.06 C289.1 ; C289.1 C288.1 C287.1 36.78,30.4 v1(36.78,30.23) ; C289.1 33.62,30.38 v1(33.78,30.23)
VDDD_1P0_CAP: length 8.6
  TOP w0.254: U7.AA11 66.83,89.48 v2(66.83,89.48) 66.83,89.47 U7.AA10 67.36,88.95 v2(67.36,88.95) 67.36,88.94 U7.AA9 ; v2(57.23,85.45) 57.6,85.45 U7.J15 ; U7.AA12 65.77,90.53 v2(65.76,90.54) ; U7.J17 56.75,85.78 v2(56.75,85.78)
  BOTTOM w0.254: v2(57.23,85.45) 57.41,85.64 C77.1 57.16,86.19 v2(56.75,85.78) ; v2(65.76,90.54) 66.04,90.54 C74.1 66.83,89.75 v2(66.83,89.48) ; C76.1 67.82,88.49 v2(67.36,88.95)
  BOTTOM w0.305: C75.1 65.35,90.14 v2(65.76,90.54)
VDDIO_PHY_3V3: length 44.5
  TOP w0.254: R663.2 v1(26.89,29.34) ; R301.2 v1(24.6,29.59) ; R302.2 v1(22.32,29.34) ; v1(31.33,35.31) 31.37,35.31 31.39,35.29 U13.41 ; R306.2 25.39,39.5 R664.2 24.48,38.61 24.22,38.35 24.22,35.69 24.58,35.33 R665.2 25.37,34.71 v1(25.35,34.69) 25.37,34.67 25.37,34.57 R688.2 ; v1(35.81,38.72) 35.78,38.69 U13.30 ; 39.64,34.79 U13.19
  TOP w0.508: 39.64,34.79 40.2,34.79 C293.1 C294.1 42.87,35.08 C250.1 C292.1 46,35.36 FB21.1 ; FB21.1 v1(46.05,34.66) ; FB21.1 v1(46.05,36.05)
  BOTTOM w0.137: C249.1 37.77,38 40.5,35.28 R129.1
  BOTTOM w0.254: v1(25.35,34.69) 24.27,34.69 22.32,32.74 v1(22.32,29.34) 22.62,29.03 24.05,29.03 v1(24.6,29.59) 25.18,29.01 26.57,29.01 v1(26.89,29.34)
  BOTTOM w0.508: v1(35.81,38.72) 35.81,38.18 C296.1 37.08,38.16 C249.1 ; C297.1 32,36.42 C295.1 31.38,35.31 31.37,35.31 v1(31.33,35.31)
2G4_ANT: length 1.6
  TOP w0.137: C529.2 118.53,9.4 M1.32
32K_OSC_EN: length 2
  TOP w0.127: Y5.1 126.04,9.64 R705.1
ADDR_LGHTSEN: length 2.4
  TOP w0.127: U31.2 123.13,47.24 R683.1 R674.2
ALS_I2C_SCL: length 1.2
  TOP w0.137: R242.1 119.56,47.89 U31.4
ALS_I2C_SDA: length 1.3
  TOP w0.137: R247.1 119.94,46.59 U31.6
ALS_INT: length 250.4
  TOP w0.102: U7.J20 v2(54.63,87.89)
  TOP w0.127: v1(119.07,46.48) R658.2 U31.5
  L6_INT_2 w0.102: v2(54.63,87.89) 53.07,87.89 52.65,87.46 52.43,87.46 52.18,87.71 51.83,87.71 51.55,87.43 51.35,87.43 49.96,88.83 47.91,88.83
  L6_INT_2 w0.127: 47.91,88.83 41.42,88.83 40.74,88.15 40.74,87.16 40.99,86.92 40.99,83.33 38.52,80.86 18.58,80.86 18.06,80.34 18.06,79.12 16.83,77.89 10.87,77.89 8.48,80.28 8.48,80.83 8.73,81.09 8.73,88.09 8.07,88.75 8.07,90.21 9.08,91.22 10.31,91.22 10.79,91.7 15.9,91.7 17.5,93.3 17.5,99.87 20.65,103.02 35.63,103.02 39.51,106.9 45.26,106.9 45.62,106.55 48.08,106.55 51.21,103.42 54.02,103.42 55.08,102.37 73.84,102.37 75.79,104.31 75.79,105.38 78.47,108.06 99.92,108.06 124.3,83.68 124.3,54.31 122.37,52.38 122.37,49.79 v1(119.07,46.48)
AUD_3V3: length 23.2
  TOP w0.254: U24.32 99.26,40.79 99.42,40.96
  TOP w0.381: v1(100.78,43.43) 100.04,43.43 FB41.2
  TOP w0.508: 99.42,40.96 99.42,41.69 98.94,42.17 C271.1 99.75,43.32 99.93,43.32 FB41.2 ; v1(111.98,32.26) R366.1
  BOTTOM w0.508: v1(100.78,43.43) 103.69,43.43 111.98,35.15 v1(111.98,32.26)
AUD_I2C_SCL: length 2.2
  TOP w0.137: U24.17 94.37,36.53 v1(93.82,35.97)
  BOTTOM w0.137: v1(93.82,35.97) 93.79,35.94 R515.1
AUD_I2C_SDA: length 3.4
  TOP w0.137: v1(94.38,35.8) 94.39,35.81 94.99,35.81 95.29,36.12 U24.18
  BOTTOM w0.137: R520.1 93.55,35.52 94.1,35.52 v1(94.38,35.8)
AUDIO_MCLK: length 69.1
  TOP w0.137: v1(74.95,38.48) 89.69,38.48 91.01,39.79 92.77,39.79 92.77,39.79 U24.11
  L3_INT_1 w0.127: v1(55.72,66.7) 53.26,66.7 53.13,66.57 53.13,62.34 56.53,58.94 56.53,56.9 v1(74.95,38.48)
  BOTTOM w0.137: v1(55.72,66.7) 55.72,68.43 51.82,72.33 51.82,74.3 R110.2 51.51,74.62
AUDIO_RXD: length 73.7
  TOP w0.137: v1(77.03,35.33) 78.2,34.16 83.02,34.16 83.72,34.86 92.07,34.86 93.44,36.23 93.44,36.96 93.77,37.29 U24.16
  L3_INT_1 w0.127: v1(52.27,61.93) 52.27,60.15 77.03,35.38 v1(77.03,35.33)
  BOTTOM w0.137: v1(52.27,61.93) 52.21,61.98 52.21,70.94 48.25,74.9 48.25,77.88
AUDIO_RXD_R: length 8.1
  TOP w0.102: U7.D16 v2(54.1,83.11)
  BOTTOM w0.102: 53.05,82.58 53.59,83.11 v2(54.1,83.11)
  BOTTOM w0.137: R485.1 49.42,78.56 51.73,80.87 52.28,80.87 53.05,81.65 53.05,82.58
AUDIO_TXC: length 2.7
  TOP w0.137: U24.12 92.7,39.29 R486.2
AUDIO_TXC_R: length 113.5
  TOP w0.102: 55.16,82.58 v2(54.63,82.58)
  TOP w0.137: v1(72.52,37.57) 90.01,37.57 R486.1
  L3_INT_1 w0.102: v2(54.63,82.58) 54.63,83.1 54.24,83.49 54.24,83.8 55.13,84.69 55.13,85.85 55.42,86.14 55.42,89.28 55.12,89.58 55.12,90.51 53.7,91.93 51.01,91.93
  L3_INT_1 w0.127: 51.01,91.93 45.88,91.93 45.58,92.23 42.19,92.23 37.78,87.82 v1(37.78,83.03)
  BOTTOM w0.137: v1(37.78,83.03) 38.94,81.87 40.84,81.87 44.51,78.2 44.51,75.09 49.39,70.21 49.39,61.37 72.52,38.24 v1(72.52,37.57)
AUDIO_TXD: length 3.4
  TOP w0.137: R483.2 91.8,36.07 92.55,36.82 92.55,37.1 93.74,38.29 U24.14
AUDIO_TXD_R: length 111.3
  TOP w0.102: v2(52.48,84.71) 52.48,84.71 U7.D19
  TOP w0.137: R483.1 90.58,36.29 v1(73.37,36.29)
  L3_INT_1 w0.102: 50.01,90.93 54.33,90.93 54.8,90.46 54.8,89.6 55.21,89.19 55.21,86.22 54.8,85.81 54.8,85.42 54.26,84.87 54.24,84.87 53.68,84.3 53.43,84.3 53.03,84.71 v2(52.48,84.71)
  L3_INT_1 w0.127: 50.01,90.93 49.9,90.93 49.88,90.96 41.42,90.96 38.68,88.22 v1(38.68,83.08)
  BOTTOM w0.137: v1(38.68,83.08) 39.35,82.41 41.3,82.41 45.05,78.66 45.05,75.44 50.03,70.46 50.03,61.4 73.37,38.05 v1(73.37,36.29)
AUDIO_TXFS: length 2.9
  TOP w0.137: U24.13 93.34,38.79 R487.2
AUDIO_TXFS_R: length 107
  TOP w0.102: U7.E19 v2(53.04,85.24)
  TOP w0.137: R487.1 90.67,37.08 v1(73.88,37.08)
  L3_INT_1 w0.102: v2(53.04,85.24) 53.57,85.24 53.99,85.65 54.27,85.65 55.01,86.39 55.01,89.11 53.44,90.68 49.76,90.68
  L3_INT_1 w0.127: v1(39.39,83.12) 39.39,88.53 41.55,90.68 49.76,90.68
  BOTTOM w0.137: v1(73.88,37.08) 73.88,38.16 73.87,38.17 73.87,38.19 50.87,61.19 50.87,70.54 45.52,75.9 45.52,79.41 41.81,83.12 v1(39.39,83.12)
BASE_PNP: length 3.4
  TOP w0.305: Q35.2 Q35.5 6.32,104.27 6.06,104.01
BAT_CTRL: length 5
  TOP w0.254: Q32.3 13.93,118.38 R614.2 R613.1
BAT_IN: length 9.8
  TOP w0.508: 10.01,127.88 J2.1 ; J2.1 11.77,127.88 ; J2.1 11.77,126.12 ; J2.1 10.01,126.12
  BOTTOM w0.508: C569.1 10.15,126.26 J2.1
BOOT_MODE0: length 122.1
  TOP w0.102: v2(66.3,82.58) 66.3,82.58 U7.P4
  TOP w0.127: v1(22.49,52.51) 22.55,52.57 26.19,52.57 27.69,54.07 33.86,54.07 39.06,59.27 44.43,59.27 v1(46.88,56.82) ; v1(6.19,36.83) 8.3,36.83 9.11,36.02 9.11,34.78 9.54,34.35 12.07,34.35 13.41,35.69 SW3.4
  L3_INT_1 w0.102: v2(66.3,82.58) 65.76,82.58 65.42,82.92 65.4,82.92 65.4,82.92 65.1,82.92 65.1,82.92 64.95,82.92 63.94,81.92 60.87,81.92 60.72,82.07 58.9,82.07 58.49,81.66 57.9,81.66 57.67,81.89 56.09,81.89 54.94,80.74 51.71,80.74
  L3_INT_1 w0.127: v1(46.88,56.82) 46.88,58.71 48.08,59.91 48.08,67.55 48.64,68.1 48.64,77.67 51.71,80.74
  BOTTOM w0.127: v1(22.49,52.51) 21.33,53.68 19.06,53.68 16,56.74 12.13,56.74 10.7,55.31 10.7,53.2 11.12,52.78 12.57,52.78 13.25,52.1 13.25,51.47 13.84,50.88 13.84,49.94 12.25,48.34 10.58,48.34 9.65,47.41 9.65,46.78 9.65,46.78 9.65,46.4 4.92,41.67 4.92,37.99 6.08,36.83 v1(6.19,36.83)
BOOT_MODE1: length 92.8
  TOP w0.102: v2(65.77,82.05) U7.P5
  TOP w0.127: SW3.3 17.14,33.15 20.74,36.74 20.74,36.77 23.44,39.48 23.44,46.58 22.05,47.97 22.05,52.7 22.31,52.96 25.8,52.96 27.23,54.38 33.78,54.38 38.95,59.55 46.31,59.55 v1(47.44,58.42)
  L3_INT_1 w0.102: 53.78,80.44 55.1,80.44 56.07,81.41 56.34,81.41 56.63,81.12 56.88,81.12 57.14,81.38 58.05,81.38 58.3,81.13 61.26,81.13 61.36,81.23 62.84,81.23 63.25,81.64 64.83,81.64 65.24,82.05 v2(65.77,82.05)
  L3_INT_1 w0.127: v1(47.44,58.42) 48.45,59.43 48.45,66.32 49.22,67.09 49.22,67.58 48.92,67.88 48.92,77.34 52.03,80.44 53.78,80.44
BT_CFG4: length 3.6
  TOP w0.127: R204.2 4.13,9.91 R697.2 6.69,9.88 SW2.8
BT_CFG5: length 3.7
  TOP w0.127: SW2.7 6.61,12.55 R698.2 4.13,12.57 R203.2
BT_CFG6: length 3.6
  TOP w0.127: SW2.6 6.69,14.96 R699.2 4.13,14.99 R206.2
BT_CFG10: length 3.5
  TOP w0.127: SW2.5 4.31,17.53 R700.2 4.26,17.53 R210.2
BT_CFG11: length 3.5
  TOP w0.127: SW2.4 6.69,20.04 R701.2 4.26,20.07 R209.2
BT_CFG12: length 3.5
  TOP w0.127: SW2.3 4.31,22.61 R702.2 3.27,22.58 R211.2
BT_CFG13: length 3.5
  TOP w0.127: SW2.2 6.69,25.12 R703.2 3.27,25.12 R213.2
BT_CFG14: length 3.5
  TOP w0.127: R212.2 3.27,27.66 R704.2 6.69,27.66 SW2.1
BT_DBG: length 6.3
  TOP w0.127: TP55.1 125.95,19.18 125.44,18.67 M1.43
BT_REG_ON: length 149.3
  TOP w0.127: v1(122.52,27.43) 123.03,27.43 127.4,23.06 127.4,17.83 126.67,17.11 126.67,17.1 126.25,16.68 124.9,16.68 123.71,17.86 121.84,17.86 121.25,17.27 M1.41 ; v1(77.46,51.31) 70.47,44.31 70.47,37.96 83.85,24.58 100.71,24.58 v1(100.82,24.47) ; U7.J6 v2(62.59,79.93)
  L6_INT_2 w0.127: v1(63.57,51.31) v1(77.46,51.31)
  BOTTOM w0.102: v2(62.59,79.93) 62.59,79.38 62.23,79.03 62.23,78.68 62.41,78.5 62.41,78.14 62.23,77.96 62.23,77.66 63.06,76.83 63.18,76.83 63.71,76.3 63.71,74.33 63.37,74 63.06,74 62.71,73.65 62.71,72.44 62.57,72.3
  BOTTOM w0.127: 62.57,72.3 62.57,70.51 63,70.08 63,64.01 58.48,59.49 56.64,59.49 55.51,58.35 55.51,57.98 62.18,51.31 v1(63.57,51.31) ; v1(100.82,24.47) 100.84,24.45 106.12,24.45 109.39,27.72 109.41,27.72 109.5,27.81 122.14,27.81 v1(122.52,27.43)
BUCK_FB: length 8.8
  TOP w0.254: C531.2 R696.2 121.65,72.92 120.98,72.24 R695.1 120.98,71.25 v1(121.09,71.14) ; U46.4 v1(122.96,66.9)
  BOTTOM w0.254: v1(122.96,66.9) 121.09,68.78 v1(121.09,71.14)
BUCK_PG: length 117.4
  TOP w0.127: U46.6 119.45,65.91 R692.2 118.63,65.09 118.52,65.09 v1(118.5,65.06) ; v1(48.1,102.53) 48.71,102.53 49.84,101.41 49.84,99.45 48.23,97.84 48.23,96.32 50.31,94.23 50.94,94.23 U7.L25
  L6_INT_2 w0.127: v1(48.1,102.53) 48.69,102.53 50.16,101.07 73.98,101.07 76.14,103.23 86.93,103.23 90.5,99.65 101.42,99.65 115.73,85.34 116.81,85.34 119.22,82.93 119.22,65.79 v1(118.5,65.06)
CAMERA_I2C_SCL: length 26.6
  TOP w0.137: v1(10.28,49.99) 10.68,50.39 16.47,50.39 17.8,51.71 19.4,51.71 21.42,53.73 24.43,53.73 25.68,54.99 R639.2 26.43,56.08 U45.4 ; v1(8.73,47.36) 8.38,47.36 6.57,45.55 J20.7
  BOTTOM w0.137: v1(10.28,49.99) 8.73,48.44 v1(8.73,47.36)
CAMERA_I2C_SDA: length 31.9
  TOP w0.137: J20.8 6.56,45.95 8.43,47.82 12.02,47.82 14.3,50.1 16.79,50.1 18.08,51.38 19.72,51.38 21.71,53.37 24.5,53.37 25.87,54.74 31.89,54.74 R638.2 31.1,56.08 U45.5
CAMERA_PWDN: length 11.1
  TOP w0.127: J20.13 7.05,47.95 7.43,48.34 7.43,50.88 8.12,51.56 9.36,51.56 v1(9.65,51.28)
  BOTTOM w0.127: v1(9.65,51.28) 10.61,50.32 R636.1 11.7,51.26 11.46,51.5 Q39.2
CAN2_RX: length 69
  TOP w0.102: v2(66.3,83.64) 66.3,83.64 66.83,83.64 U7.T5
  TOP w0.137: v1(73.37,25.78) 73.67,25.49 U25.4
  BOTTOM w0.137: v2(66.3,83.64) 66.83,83.64 67.97,82.5 68.75,82.5 70.43,80.81 72.39,80.81 79.32,73.89 79.32,33.22 73.37,27.27 v1(73.37,25.78)
CAN2_TX: length 68.8
  TOP w0.102: U7.T6 66.83,84.18 v2(66.83,84.17)
  TOP w0.137: U25.1 75.62,25.49 v1(75.91,25.78)
  BOTTOM w0.137: v2(66.83,84.17) 67.36,84.17 68.27,83.27 68.8,82.74 68.82,82.74 68.83,82.73 68.85,82.73 70.48,81.1 72.74,81.1 80.24,73.6 80.24,30.11 v1(75.91,25.78)
CAN_STB: length 206
  TOP w0.127: v1(56.31,27.85) 57.67,29.21 75.66,29.21 78.48,26.39 78.48,22.5 77.85,21.87 R224.1 77.11,21.94 75.62,21.94 U25.8 ; R381.1 42.24,91.44 35.78,91.44 34.65,90.31 v1(29.05,90.31)
  L3_INT_1 w0.127: v1(56.31,27.85) 51.83,23.37 23.59,23.37 15.83,15.61 6.39,15.61 2.72,19.27 2.72,32.99 3.46,33.73 3.46,40.44 3.71,40.7 3.71,52.28 2.79,53.2 2.79,81.2 5.21,83.62 5.21,89.5 6.62,90.9 10.64,90.9 11.31,91.58 16.82,91.58 19.05,93.81 20.26,93.81 20.63,93.45 20.63,92.22 21.63,91.22 21.63,91.22 22.53,90.31 v1(29.05,90.31)
CANH: length 14.7
  TOP w0.137: U25.7 74.97,20.25 R245.2 75.66,19.68 76.42,18.92 C282.1 75.44,15.51 P14.2 75.44,14.08 75.33,13.97 75.33,8.4 J19.7
CANL: length 12.6
  TOP w0.137: U25.6 74.32,20.38 R246.2 73.5,19.68 72.74,18.92 72.74,16.61 C281.1 74.48,14.87 P13.2 74.76,14.19 74.76,11.94 J19.2
CAP_2G4_ANT: length 1.9
  TOP w0.137: C529.1 118.54,8.57 L8.1 118.54,6.68 C530.2
CAP_IND_2G4_ANT: length 1
  TOP w0.137: C530.1 J10.1
CCM_CLK1_N: length 7.6
  TOP w0.127: U7.Y1 71.62,83.1 72.42,83.1 72.59,83.26 75.83,83.26 76.07,83.02 77.78,83.02 TP8.1
CCM_CLK1_P: length 6.2
  TOP w0.127: TP7.1 76.24,83.57 72.43,83.57 72.29,83.42 71.83,83.42 71.08,84.18 U7.Y2
CCM_CLK2: length 11.8
  TOP w0.102: U7.W3 70.01,84.18
  TOP w0.127: 70.01,84.18 70.01,84.16 71.38,82.8 72.63,82.8 72.79,82.96 75.52,82.96 R641.1 76.39,82.18 76.86,82.65 79.16,82.65 TP9.1
CLK_32K: length 1.6
  TOP w0.137: R706.1 124.28,13.84 Y5.3
CLKGEN_OE0_B: length 2.1
  TOP w0.254: R155.1 76.55,98.17 77.02,98.17 U42.12
CLKGEN_OE1_B: length 2.3
  TOP w0.127: U42.19 80.1,95.08 80.1,93.85 R449.1
CLKGEN_Q0_N: length 2
  TOP w0.104: U42.14 77.5,96.68 arc(77.43,96.67) 77.36,96.63 77.31,96.57 arc(77.07,96.41) 76.78,96.35 76.52,96.35 arc(76.5,96.35) 76.47,96.34 76.39,96.29 76.33,96.23 arc(76.3,96.18) 76.29,96.12 R598.1
CLKGEN_Q0_P: length 2
  TOP w0.104: U42.13 77.23,96.96 arc(77.22,96.89) 77.18,96.84 77.17,96.83 arc(77.17,96.83) 77.17,96.83 77.11,96.77 arc(76.96,96.67) 76.78,96.63 76.53,96.63 arc(76.45,96.63) 76.37,96.6 arc(76.35,96.6) 76.34,96.59 arc(76.33,96.59) 76.32,96.58 76.21,96.5 76.15,96.45 arc(76.12,96.42) 76.08,96.42 R597.1
CLKGEN_Q1_N: length 2.1
  TOP w0.104: 79,95.27 78.94,95.27 arc(78.84,95.25) 78.75,95.19 arc(78.66,95.09) 78.59,94.97 arc(78.5,94.8) 78.38,94.65 arc(78.38,94.65) 78.38,94.65 78.28,94.55 arc(78.15,94.45) 78,94.37 arc(77.99,94.37) 77.99,94.36 arc(77.87,94.26) 77.83,94.12 77.83,93.94 arc(77.85,93.85) R633.1
CLKGEN_Q1_P: length 2.1
  TOP w0.104: U42.17 78.64,95.6 arc(78.62,95.49) 78.56,95.39 arc(78.44,95.25) 78.34,95.09 arc(78.26,94.94) 78.15,94.81 78.08,94.75 arc(78,94.68) 77.9,94.63 arc(77.9,94.63) 77.89,94.63 arc(77.88,94.62) 77.87,94.62 arc(77.82,94.59) 77.77,94.55 arc(77.69,94.51) 77.6,94.5 R632.1
CLKGEN_XIN: length 7.4
  TOP w0.137: U42.1 81.9,98.17 81.9,98.37 81.9,98.37 81.9,98.51 83.12,99.72 C402.1 83.78,99.74 83.78,100.45 85.11,101.78 85.64,101.78 X4.1
CLKGEN_XOUT: length 7.6
  TOP w0.137: X4.2 84.9,102.52 84.9,102.08 83.5,100.68 C403.1 82.77,100.65 82.77,99.79 81.4,98.42 81.4,98.39 81.33,98.31
CODEC_GPIO_INT: length 97.4
  TOP w0.127: U7.K24 53.57,91.07 51.12,93.52 50.85,93.52 v1(50.84,93.53) ; v1(81.49,35.82) 82.92,35.82 83.59,35.15 91.9,35.15 92.93,36.18 92.93,37.03 93.69,37.79 U24.15
  L6_INT_2 w0.127: v1(74.77,35.69) 74.77,35.69 74.9,35.82 v1(81.49,35.82)
  BOTTOM w0.137: v1(50.84,93.53) 50.84,92.02 45.92,87.1 45.92,85.82 46.04,85.7 46.04,85.33 45.92,85.21 45.92,76.49 51.57,70.84 51.57,60.96 74.77,37.76 v1(74.77,35.69)
COLL_GPIO3: length 24.2
  TOP w0.127: R752.2 v1(12.54,93.14)
  BOTTOM w0.127: v1(12.54,93.14) 12.54,90.39 10.11,87.96 7.81,87.96 7.49,87.64 7.49,83.57 9.25,81.81 13.07,81.81 13.84,81.04 Q41.3 15.02,79.32 R763.1
COLL_PMIC_LED: length 2.7
  TOP w0.127: Q40.3 2.39,91.39 D33.1
COLLECTOR_PNP: length 2.6
  TOP w0.254: Q35.3 9.47,104.92 9.72,105.17 R616.2 10.09,106.54 Q34.3
CSENS1_I2C_SCL: length 1.5
  TOP w0.137: R723.1 18.56,63.4 U50.6
CSENS1_I2C_SDA: length 1.6
  TOP w0.137: R724.1 19.22,63.53 U50.7
CSENS1_PV: length 55.1
  TOP w0.102: U7.L23 54.1,90.54 v2(54.1,90.54)
  TOP w0.127: R727.1 21.86,65.94 21.86,65.36 v1(22.83,64.38)
  TOP w0.254: R727.1 22.03,66.22 U50.10
  L6_INT_2 w0.127: v2(54.1,90.54) 53.48,89.91 36.17,89.91 v1(35.65,90.42)
  BOTTOM w0.127: v1(22.83,64.38) 23.68,65.22 24.83,65.22 35.65,76.05 v1(35.65,90.42)
CSENS2_A0: length 1.7
  BOTTOM w0.127: R732.1 19.87,63.95 U52.5
CSENS2_I2C_SCL: length 1.9
  BOTTOM w0.137: R726.1 19.22,63.02 U52.6
CSENS2_I2C_SDA: length 1.9
  BOTTOM w0.137: R725.1 18.56,63.15 U52.7
CSENS2_PV: length 87.5
  TOP w0.127: U7.L24 54.1,91.58 51.99,93.69 51.99,94.74 50.64,96.09 v1(49.57,96.09)
  L6_INT_2 w0.127: v1(49.57,96.09) 48.37,97.29 26.79,97.29 25.56,96.07 22.63,96.07 v1(22.38,95.82)
  BOTTOM w0.127: U52.10 15.49,66.22 R731.1 12.94,65.81 5.35,73.4 5.35,88.16 5.72,88.53 10.29,88.53 12.1,90.34 12.1,93.32 12.48,93.71 13.61,93.71 15.23,95.33 21.89,95.33 v1(22.38,95.82)
CSI_AGND: length 9
  TOP w0.127: J20.4 7.78,44.35 8.01,44.13 v1(8.04,44.13)
  TOP w0.254: v1(6.88,41.68) 6.8,41.76 6.8,43.41 6.66,43.55 J20.2
  TOP w0.381: v1(6.88,41.68) 7.79,41.68 R269.1
  BOTTOM w0.254: v1(8.04,44.13) 6.82,42.9 6.82,41.95 6.88,41.89 v1(6.88,41.68)
CSI_I2C_SCL: length 1.9
  TOP w0.137: U45.1 26.94,57.58 26.74,57.78 R516.1
CSI_I2C_SDA: length 2
  TOP w0.137: U45.8 30.7,57.58 31.54,58.42 R521.1
CSI_PIN30: length 3.4
  TOP w0.127: R622.1 2.03,40.85 2.03,42.76 2.42,43.15 J20.30
CSI_PWDN: length 68.5
  TOP w0.127: U7.G25 50.88,90.04 47.59,90.04 43.53,94.11 40.81,94.11 v1(40.35,93.65)
  L3_INT_1 w0.127: v1(40.35,93.65) 39.9,93.65 20.72,74.47 16.04,74.47 13.94,72.36 13.94,67.56 12.71,66.34 v1(12.71,55.58)
  BOTTOM w0.127: v1(12.71,55.58) 11.93,55.58 11.8,55.45 R637.1 11.8,53.68 Q39.3
CSI_RESET: length 4.4
  TOP w0.127: R630.1 C456.1
  TOP w0.137: C456.1 8.27,48.08 6.54,46.35 J20.9
CSI_VDD_1V8: length 25
  TOP w0.203: v1(8.91,50.16) 8.91,49.83 R630.2
  TOP w0.254: J20.28 2.01,43.95
  TOP w0.406: v1(4.06,40.41) 4.04,40.43 R622.2 3.41,39.07 C447.1 2.32,39.07 C446.1 0.89,40.04 0.89,42.83 2.01,43.95
  TOP w0.508: FB36.1 4.43,39.14 4.36,39.07 C447.1
  L3_INT_1 w0.203: v1(4.06,40.41) 4.06,46.42 7.17,49.53 8.27,49.53 v1(8.91,50.16)
CSI_XCLK: length 4.1
  TOP w0.127: J20.25 2.27,45.15 2.14,45.02 1.47,45.02 v1(1.44,45.05)
  BOTTOM w0.127: v1(1.44,45.05) 1.48,45 2.17,45 3.46,46.29 Y4.3
CSI_XCLK_OE: length 1.8
  BOTTOM w0.406: R623.2 5.36,50.38 Y4.1
D_USB_DN: length 3.9
  TOP w0.127: R160.2 122.86,107.81 123.64,107.81 P19.2 124.19,107.8 125.15,107.8 125.34,107.62 J11.2
D_USB_DP: length 3.9
  TOP w0.127: R158.2 122.81,108.09 123.64,108.09 P18.2 124.21,108.08 125.14,108.08 125.33,108.27 J11.3
DBG_DA: length 3.3
  BOTTOM w0.127: R165.1 100.58,118.62 101.85,118.62 102.48,117.99 U18.2
DBG_RXLED1: length 2.3
  TOP w0.254: D8.2 v1(128.06,121.67)
  BOTTOM w0.254: R161.1 v1(128.06,121.67)
DBG_RXLED2: length 2.5
  TOP w0.254: D10.2 v1(128.14,116.71)
  BOTTOM w0.254: R166.1 v1(128.14,116.71)
DBG_TXLED1: length 2.4
  TOP w0.254: v1(128.09,119.25) D9.2
  BOTTOM w0.254: R162.1 v1(128.09,119.25)
DBG_TXLED2: length 2.7
  TOP w0.254: D11.2 v1(128.23,114.43)
  BOTTOM w0.254: R167.1 v1(128.23,114.43)
DBG_XTIN: length 10.2
  BOTTOM w0.137: U18.43 99.15,113.13 98.84,112.82 R164.1 96.31,112.82 C243.2 93.6,112.81 91.41,110.62 X5.1
DBG_XTOUT: length 9.1
  BOTTOM w0.137: X5.3 93.95,114.05 94.33,113.67 96.12,113.67 C244.2 96.36,113.78 R164.2 98.94,113.78 99.09,113.63 U18.44
DC34_SEL: length 3.5
  TOP w0.127: U5.17 17.08,90.25 16.86,90.47 16.56,90.47 16.38,90.64 16.38,90.64 16.13,90.89 16.13,90.89 15.84,91.18 14.91,91.18 14.55,91.54 R37.2
DC_SW: length 3.2
  TOP w0.508: R12.1 SW1.1
DC_SW_CTL: length 32.4
  TOP w0.203: R12.2 v1(42.64,121.95)
  TOP w0.254: Q2.3 29.66,105.11 30.36,104.41 33.74,104.41
  TOP w0.381: C394.2 34.88,104.43 33.76,104.43 R539.1 33.74,104.41 ; C394.2 v1(34.89,103.75) ; C394.2 37.31,104.42 D20.1
  L6_INT_2 w0.203: v1(34.89,103.75) 34.89,114.2 v1(42.64,121.95)
DDR_SDCLK0_N: length 4.7
  TOP w0.102: U7.AD25 60.46,98.63
  TOP w0.104: 60.46,98.63 60.27,98.83 60.27,99.48 60.8,100.01 60.8,100.29 60.67,100.42 59.63,101.46 59.63,101.91 R618.1
DDR_SDCLK0_P: length 5.3
  TOP w0.104: U7.AD24 60.83,98.66 60.55,98.94 60.55,99.36 61.08,99.9 61.08,100.41 59.91,101.58 59.91,101.9 R617.1
DDR_VREF: length 4.8
  TOP w0.127: U9.M8 v2(50.95,111.62)
  TOP w0.254: v2(68.12,112.43) 67.71,112.02 U8.M8 ; U8.H1 73.54,108.82 v2(74.03,109.31) ; U7.AC13 v2(66.3,92.13)
  TOP w0.305: v2(56.79,107.77) 56.79,108.05 56.15,108.69 U9.H1
  BOTTOM w0.254: v2(66.3,92.13) 66.88,92.71 66.92,92.71
  vias: v3(78.25,110.94) v3(78.26,110.18)
DEBUG_5V0: length 24.5
  BOTTOM w0.254: R157.1 v1(97.53,115.7)
  BOTTOM w0.305: U18.42 99.4,112.63 99.07,112.3 ; U18.4 103.48,118.23 103.22,118.49 102.98,118.25 U18.3 ; v1(110.89,114.27) 111.26,114.65 R294.2 111.26,115.13 U18.14 ; 104.48,107.58 U18.31
  BOTTOM w0.381: R161.2 R162.2 R166.2 R167.2 125.04,113.74 v1(125.04,113.69)
  BOTTOM w0.406: C227.1 99.07,112.29 99.07,112.3
  BOTTOM w0.508: 103.22,118.49 103.22,119.15 C361.1 101.85,119.28 C226.1 v1(100.87,119.43) 100.87,119.48 100.36,119.99 R165.2 ; 104.48,107.58 104.74,107.31 C228.1 104.31,106.53 v1(103.92,106.92) ; C227.1 v1(97.63,111.73)
  vias: v1(120.92,102.23) v1(121.77,102.91)
DRAM0_ZQ: length 3.5
  TOP w0.137: U8.L8 67.95,111.22 68.36,111.62 v2(69.2,111.62)
  BOTTOM w0.137: v2(69.2,111.62) 69.2,112.39 69.33,112.52 R83.2
DRAM0_ZQ1: length 1.5
  TOP w0.127: v2(66.36,111.2) 66.38,111.22 U8.L9
  BOTTOM w0.137: v2(66.36,111.2) 66.21,111.05 R81.1
DRAM1_ZQ: length 2.7
  TOP w0.127: U9.L8 50.35,111.22
  TOP w0.137: 50.35,111.22 49.95,110.82 v2(48.96,110.82)
  BOTTOM w0.137: R84.2 48.59,110.44 v2(48.96,110.82)
DRAM1_ZQ1: length 1.8
  TOP w0.127: U9.L9 49.28,111.68 v2(48.98,111.68)
  BOTTOM w0.137: v2(48.98,111.68) 48.35,111.68 R82.2
DRAM_ADDR0: length 54.3
  TOP w0.102: U7.AB19 62.59,94.77 v2(62.58,94.77)
  TOP w0.137: U8.N3 v2(71.3,113.22) ; U9.N3 v2(54.15,113.22)
  L6_INT_2 w0.137: v2(71.3,113.22) 70.74,113.22 68.65,115.31 66.72,115.31 66.08,115.96 65.36,115.96 64.22,114.82 64.22,114.68 64.09,114.55 64.09,113.99 63.54,113.44 v2(63.53,113.44) 63.49,113.4 62.85,113.4 62.27,113.98 61.96,113.98 61.8,113.82 61.34,113.82 60.52,112.99 57.55,112.99 57.32,113.22 56.86,113.22 56.46,112.82 U9.N3 v2(54.15,113.22)
  BOTTOM w0.102: 63.23,95.94 63.19,95.94 62.58,95.33 v2(62.58,94.77)
  BOTTOM w0.137: 63.23,95.94 63.87,96.58 63.87,98.21 63.15,98.93 63.15,99.74 62.67,100.22 62.67,100.4 63.56,101.3 63.56,101.98 63.22,102.32 63.22,103.55 63.46,103.79 63.89,103.79 64.07,103.61 64.07,99.06 64.21,98.91 64.41,98.91 64.55,99.05 64.55,104.38 64.54,104.39 64.54,109.02 64.12,109.44 64.12,109.51 63.82,109.82 63.82,110.23 63.11,110.94 63.11,111.13 63.16,111.18 63.16,111.53 62.96,111.74 62.96,112.87 v2(63.53,113.44)
DRAM_ADDR1: length 58.5
  TOP w0.102: v2(64.18,93.19) U7.AB16
  TOP w0.137: v2(61.91,120.68) 66.13,120.68 70.15,116.66 70.15,114.72 69.05,113.62 U8.P7 ; U9.P7 v2(50.97,113.99)
  L3_INT_1 w0.137: v2(50.97,113.99) 57.66,120.68 v2(61.91,120.68) 62.23,119.95 64.03,118.15 64.03,111.33 62.73,110.03 62.73,105.74 63.25,105.22 63.25,102.12 63.61,101.75 63.61,95.87 64.55,94.93 64.55,94.1 64.18,93.72 v2(64.18,93.19)
DRAM_ADDR2: length 55.4
  TOP w0.102: v2(63.65,94.78) 63.65,94.77 U7.AC18
  TOP w0.137: U9.P3 v2(54.15,114.02) ; U8.P3 v2(71.22,114.1)
  L6_INT_2 w0.137: v2(71.22,114.1) 70.83,114.1 67.96,116.97 64.3,116.97 63.45,116.11 63.45,115.92 63.62,115.75 63.62,115.54 63.37,115.3 v2(63.37,114.98) 62.32,114.98 62.22,114.89 60.66,114.89 59.54,113.77 58.27,113.77 57.22,114.82 56.81,114.82 56.55,114.57 56.26,114.57 55.31,113.62 55.12,113.62 U9.P3 v2(54.15,114.02)
  BOTTOM w0.137: v2(63.37,114.98) 62.53,114.98 62.13,115.38 62.13,115.74 62.67,116.28 62.67,118.76 62.8,118.9 63.48,118.9 63.62,118.76 63.62,115.47 64.69,114.39 64.69,113.17 63.98,112.45 63.98,111.41 64.71,110.68 64.71,110.41 65.49,109.63 65.49,98.59 64.8,97.91 64.8,95.93 v2(63.65,94.78)
